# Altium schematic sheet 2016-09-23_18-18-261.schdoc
size 356 x 185 mm; SheetNumber: 1; SheetTotal: 1
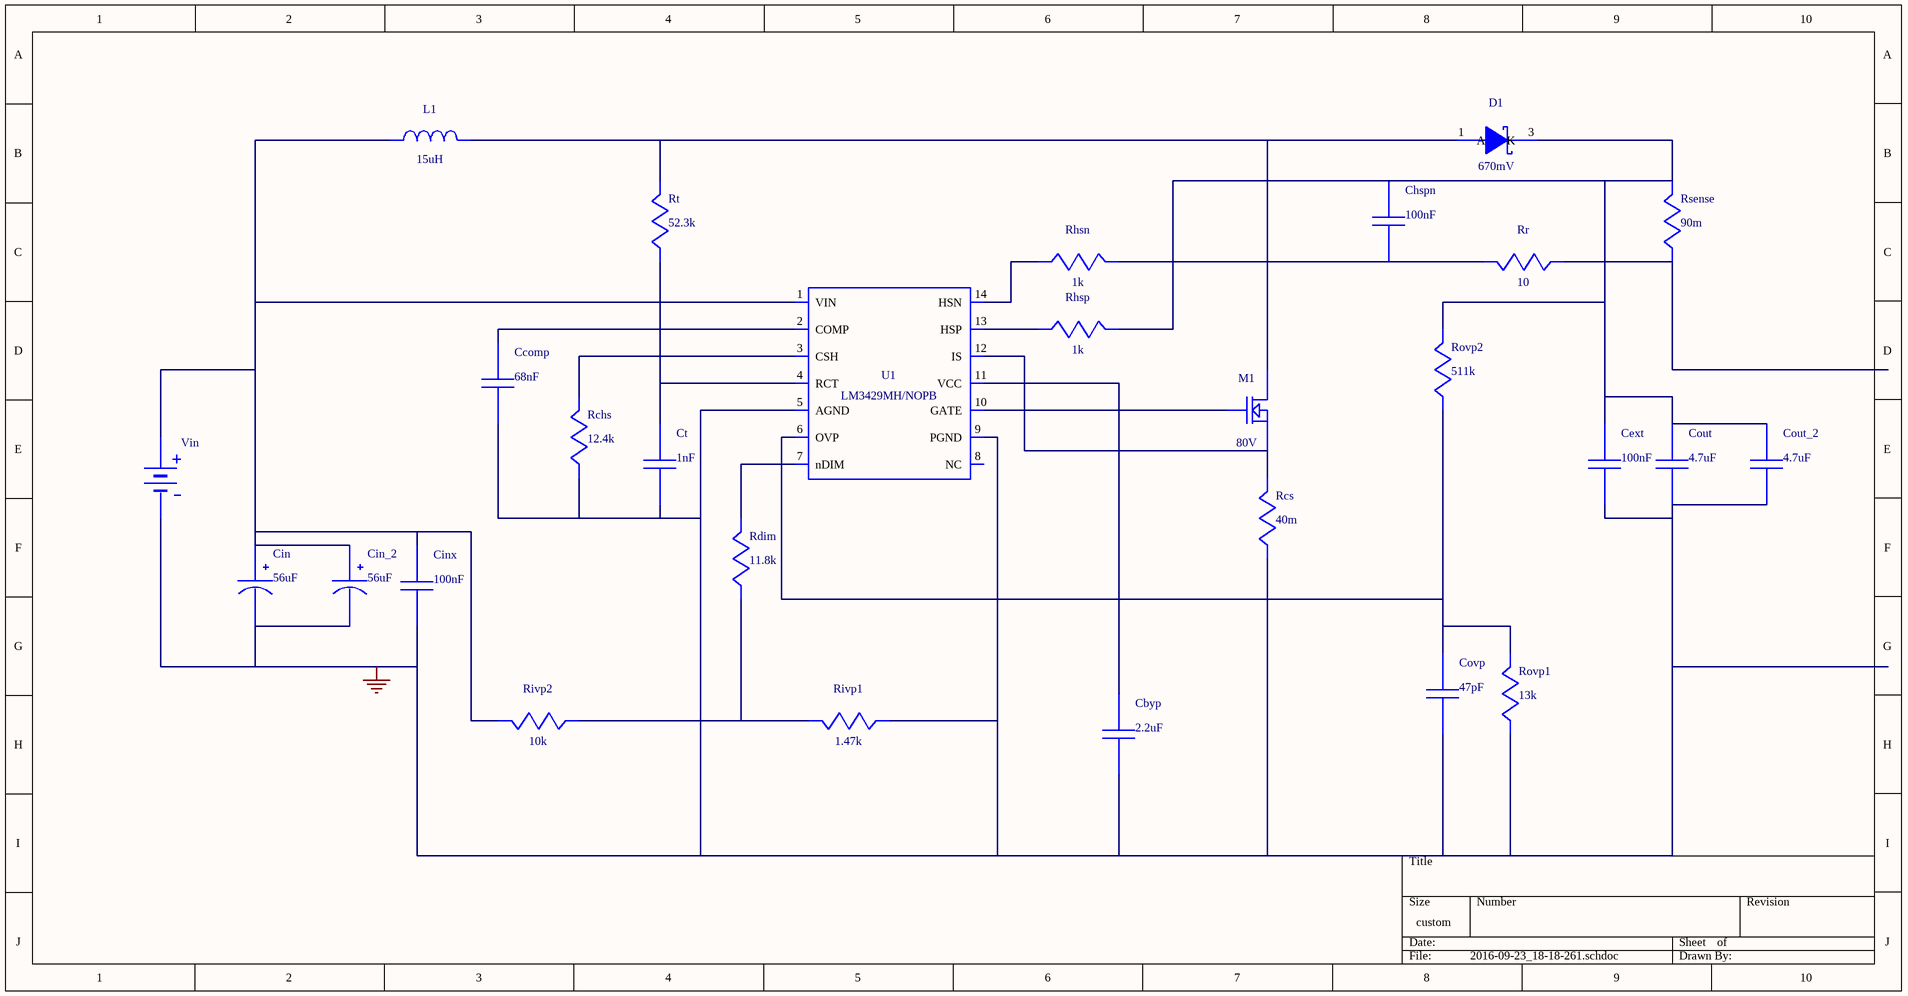
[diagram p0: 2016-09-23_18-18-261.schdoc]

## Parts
Cbyp  value 2.2uF  (hidden comment: EMK212B7225KG-T)
Ccomp  value 68nF  (hidden comment: GRM155R61A683KA01D)
Cext  value 100nF  (hidden comment: C0805C104K5RACTU)
Chspn  value 100nF  (hidden comment: GRM21BR71E104KA01L)
Cin  value 56uF  (hidden comment: UUD1V560MCL1GS)
Cin_2  value 56uF  (hidden comment: UUD1V560MCL1GS)
Cinx  value 100nF  (hidden comment: C0603C104K5RACTU)
Cout  value 4.7uF  (hidden comment: GRM31CR71H475KA12L)
Cout_2  value 4.7uF  (hidden comment: GRM31CR71H475KA12L)
Covp  value 47pF  (hidden comment: C0805C470K5GACTU)
Ct  value 1nF  (hidden comment: CL21C102JBCNFNC)
D1  value 670mV  (hidden comment: FSV8100V)
L1  value 15uH  (hidden comment: MSS1210-153MEB)
M1  value 80V  (hidden comment: BSC340N08NS3 G)
Rchs  value 12.4k  (hidden comment: CRCW040212K4FKED)
Rcs  value 40m  (hidden comment: CSRN2010FK40L0)
Rdim  value 11.8k  (hidden comment: CRCW040211K8FKED)
Rhsn  value 1k  (hidden comment: CRCW04021K00FKED)
Rhsp  value 1k  (hidden comment: CRCW04021K00FKED)
Rivp1  value 1.47k  (hidden comment: CRCW04021K47FKED)
Rivp2  value 10k  (hidden comment: CRCW040210K0FKED)
Rovp1  value 13k  (hidden comment: CRCW040213K0FKED)
Rovp2  value 511k  (hidden comment: CRCW0402511KFKED)
Rr  value 10  (hidden comment: CRCW040210R0FKED)
Rsense  value 90m  (hidden comment: CRM0805-FW-R090ELF)
Rt  value 52.3k  (hidden comment: CRCW040252K3FKED)
U1  LM3429MH  (value not drawn)
Vin  WB_BATTERY  (value not drawn)

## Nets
0: Cbyp.2 Ccomp.2 Cext.2 Cin.2(-) Cin_2.2(-) Cinx.2 Cout.2 Cout_2.2 Covp.2 Ct.2 Rchs.2 Rcs.2 Rivp1.2 Rovp1.2 U1.5(AGND) U1.9(PGND) U1.15(DAP) Vin.2(-)
NetCbyp_1: Cbyp.1 U1.11(VCC)
NetCcomp_1: Ccomp.1 U1.2(COMP)
NetCext_1: Cext.1 Chspn.1 Cout.1 Cout_2.1 D1.3(K) Rhsp.1 Rovp2.1 Rsense.1
NetChspn_2: Chspn.2 Rhsn.1 Rr.1
NetCin_1: Cin.1(+) Cin_2.1(+) Cinx.1 L1.1 Rivp2.1 U1.1(VIN) Vin.1(+)
NetCovp_1: Covp.1 Rovp1.1 Rovp2.2 U1.6(OVP)
NetCt_1: Ct.1 Rt.2 U1.4(RCT)
NetD1_1: D1.1(A) D1.2(A) L1.2 M1.5(Drain) M1.6(Drain) M1.7(Drain) M1.8(Drain) M1.9(Drain) Rt.1
NetM1_1: M1.1(Source) M1.2(Source) M1.3(Source) Rcs.1 U1.12(IS)
NetM1_4: M1.4(Gate) U1.10(GATE)
NetRchs_1: Rchs.1 U1.3(CSH)
NetRdim_1: Rdim.1 U1.7(nDIM)
NetRdim_2: Rdim.2 Rivp1.1 Rivp2.2
NetRhsn_2: Rhsn.2 U1.14(HSN)
NetRhsp_2: Rhsp.2 U1.13(HSP)
NetRr_2: Rr.2 Rsense.2

Not connected (* = marked no-connect by the designer): U1 8(NC)

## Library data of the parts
Cbyp = EMK212B7225KG-T: Manufacturer Name: Taiyo Yuden
Ccomp = GRM155R61A683KA01D: GRM155R61A683KA0; Manufacturer Name: MuRata
Cext = C0805C104K5RACTU: Manufacturer Name: Kemet
Chspn = GRM21BR71E104KA01L: GRM21BR71E104KA0; Manufacturer Name: MuRata
Cin Cin_2 = UUD1V560MCL1GS: Manufacturer Name: Nichicon
Cinx = C0603C104K5RACTU: Manufacturer Name: Kemet
Cout Cout_2 = GRM31CR71H475KA12L: GRM31CR71H475KA1; Manufacturer Name: MuRata
Covp = C0805C470K5GACTU: Manufacturer Name: Kemet
Ct = CL21C102JBCNFNC: Manufacturer Name: Samsung Electro-Mechanics
D1 = FSV8100V: Manufacturer Name: Fairchild Semiconductor
L1 = MSS1210-153MEB: Unknown; Manufacturer Name: Coilcraft
M1 = BSC340N08NS3 G: Manufacturer Name: Infineon Technologies
Rchs = CRCW040212K4FKED: Manufacturer Name: Vishay-Dale
Rcs = CSRN2010FK40L0: Manufacturer Name: Stackpole Electronics Inc
Rdim = CRCW040211K8FKED: Manufacturer Name: Vishay-Dale
Rhsn Rhsp = CRCW04021K00FKED: Manufacturer Name: Vishay-Dale
Rivp1 = CRCW04021K47FKED: Manufacturer Name: Vishay-Dale
Rivp2 = CRCW040210K0FKED: Manufacturer Name: Vishay-Dale
Rovp1 = CRCW040213K0FKED: Manufacturer Name: Vishay-Dale
Rovp2 = CRCW0402511KFKED: Manufacturer Name: Vishay-Dale
Rr = CRCW040210R0FKED: Manufacturer Name: Vishay-Dale
Rsense = CRM0805-FW-R090ELF: CRM0805-FW-R090E; Manufacturer Name: Bourns
Rt = CRCW040252K3FKED: Manufacturer Name: Vishay-Dale
U1 = LM3429MH: LM3429MH/NOPB; Manufacturer Name: Texas Instruments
